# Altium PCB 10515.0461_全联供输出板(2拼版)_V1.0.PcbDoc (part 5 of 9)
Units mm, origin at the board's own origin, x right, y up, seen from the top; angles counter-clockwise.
Board outline 283.88 x 134.8 mm, 2 copper layers (Top Layer, Bottom Layer); 298 components, 0 nets, 1264 pads, 970 vias.
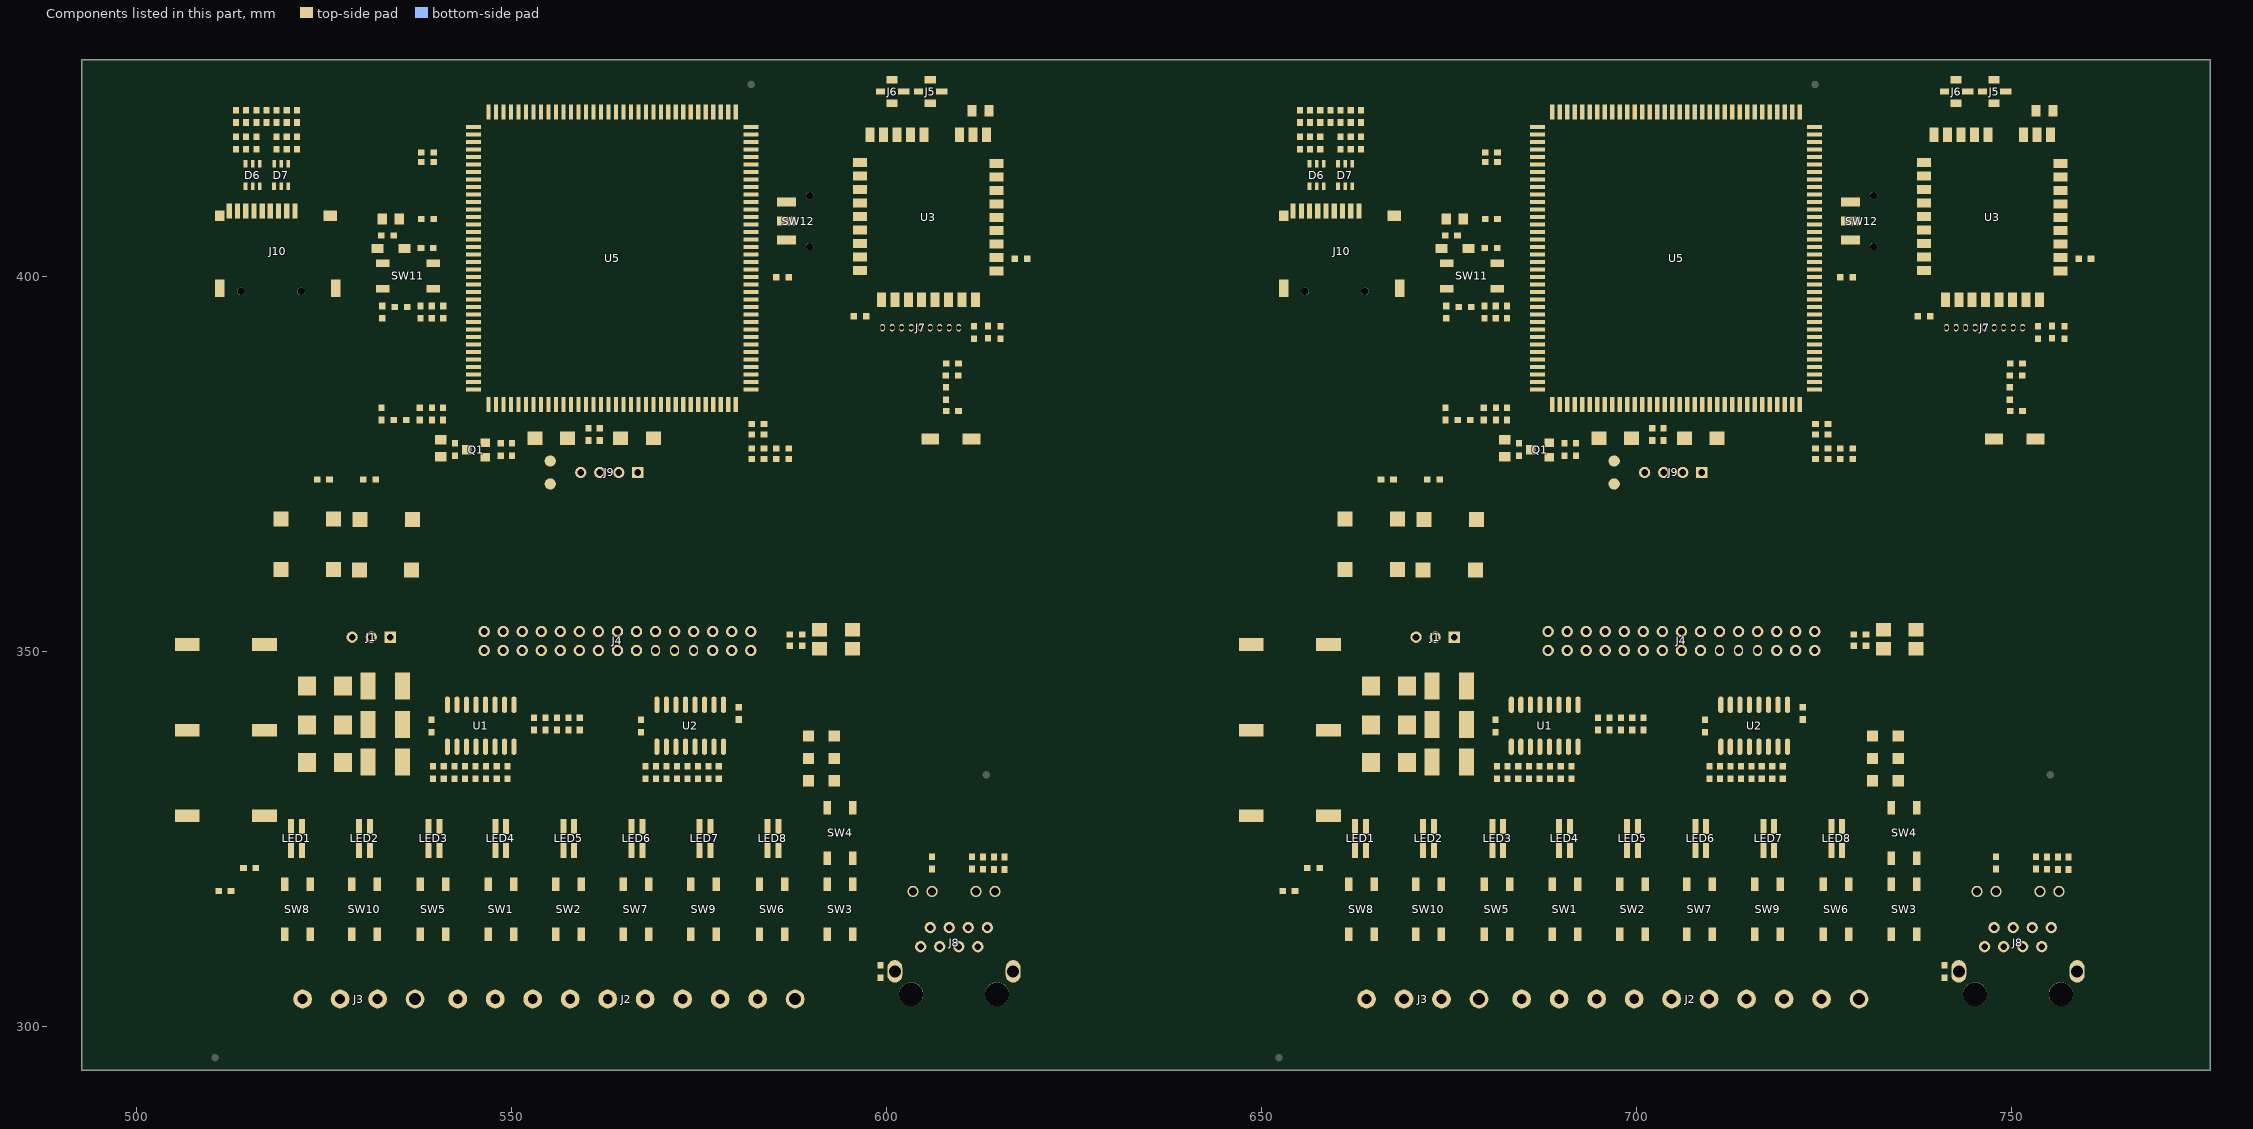
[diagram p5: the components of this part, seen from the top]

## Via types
v1: diameter 0.7, hole 0.4, Top Layer to Bottom Layer, tented both sides, 970 vias

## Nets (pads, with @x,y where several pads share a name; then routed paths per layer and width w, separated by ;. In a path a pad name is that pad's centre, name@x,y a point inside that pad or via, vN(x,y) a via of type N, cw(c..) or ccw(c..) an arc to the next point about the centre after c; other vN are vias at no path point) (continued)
copper on no net: (continued)
  Top Layer w0.65: 536.575,356.309 537.21,356.309 538.46,356.309 538.849,355.92 538.869,355.92 538.944,355.845 539.115,355.674 ; 540.537,375.918 542.277,375.918 542.417,376.058 ; 540.816,380.82 547.865,380.82 ; 540.884,375.699 cw(c541.413,375.169) 541.413,375.918 cw(c541.413,376.666) 540.884,376.137 ; 541.975,375.918 ccw(c541.975,376.461) 542.359,376.077 ; 542.417,377.589 cw(c542.417,375.556) 543.854,376.994 ; 542.417,377.709 543.14,377.709 543.981,376.867 ; 542.441,377.593 cw(c542.762,376.571) 543.52,377.328 ; 543.671,376.867 ccw(c542.923,376.867) 543.452,377.396 ccw(c543.981,377.925) 543.981,377.177 ; 546.671,376.058 548.513,376.058 550.037,376.058 ; 546.719,375.693 cw(c547.6,374.812) 547.6,376.058 ; 547.865,382.91 547.865,381.214 547.865,380.82 ; 548.738,380.82 547.865,380.82 ; v1@585.47,339.443 ccw(c585.47,340.73) 586.38,339.82 ; v1@586.105,339.443 ccw(c586.105,340.73) 587.015,339.82 ; v1@586.13,339.418 cw(c587.723,339.418) 586.597,340.545 ; v1@586.535,342.321 cw(c585.122,340.908) 587.121,340.908 ; v1@586.535,342.357 ccw(c585.122,343.77) 587.121,343.77 ; v1@586.614,339.443 ccw(c586.642,340.659) 587.502,339.799 ; v1@586.638,339.418 cw(c588.231,339.418) 587.105,340.545 ; 587.058,350.755 587.058,352.245 ; v1@587.103,339.436 ccw(c586.141,340.398) 587.502,340.398 ; 587.121,340.561 585.978,339.418 v1(585.47,339.418) ; 587.121,341.069 v1(585.47,339.418) ; 587.121,346.277 cw(c588.712,346.277) 587.587,347.401 cw(c588.549,346.439) 588.549,347.8 ; 587.121,346.904 cw(c587.613,346.904) v1@587.571,347.394 ; 587.195,347.239 cw(c587.569,346.865) v1@587.569,347.394 ; 587.502,343.557 cw(c589.526,343.557) v1@588.095,344.988 ; 587.502,346.455 ccw(c589.526,346.455) v1@588.095,345.024 ; v1@587.594,347.419 cw(c588.123,347.419) 587.749,347.793 ; 588.582,350.721 590.906,350.721 ; 588.625,350.721 cw(c588.625,348.032) 590.526,349.933 ; 589.228,347.8 cw(c589.228,346.135) v1@590.405,347.312 ; 589.845,352.245 ccw(c589.845,353.657) 590.994,352.836 ; v1@590.441,347.312 cw(c591.618,346.135) 591.618,347.8 ; 590.465,353.214 cw(c588.582,354.56) 588.582,352.245 590.652,352.245 ; 590.652,352.499 591.144,352.991 ; 590.906,350.467 591.033,350.34 ; 593.826,348.155 ccw(c591.653,350.328) 594.726,350.338 ; 594.741,348.181 595.401,348.841 595.401,350.34 595.401,352.88 ; 594.868,348.633 cw(c596.242,348.633) 595.579,349.836 ; 594.868,348.689 594.868,352.347 ccw(c596.795,352.347) 595.644,350.801 ; 594.868,349.197 593.471,347.8 593.344,347.8 ; 594.868,350.446 cw(c597.735,350.446) 595.708,352.473 ; 594.868,352.016 cw(c596.165,352.016) 595.248,352.933 ; 594.93,349.259 ccw(c593.855,350.335) 595.376,350.34 ; 594.994,349.933 cw(c594.013,348.952) 595.401,348.952 cw(c596.789,348.952) 595.808,349.933 ; 594.994,350.747 ccw(c594.013,351.728) 595.401,351.728 ccw(c596.789,351.728) 595.808,350.747 ; 594.994,352.473 cw(c594.013,351.492) 595.401,351.492 cw(c596.789,351.492) 595.808,352.473 ; 599.392,419.415 ccw(c598.922,419.885) 599.586,419.885 ccw(c600.25,419.885) 599.78,419.415 ; 599.586,418.871 599.586,421.568 599.16,421.994 599.16,424.635 599.16,425.879 599.466,426.185 600.71,426.185 601.827,426.185 602.26,425.752 602.26,424.635 ; 600.71,423.085 601.386,422.409 601.386,418.871 ; 600.836,422.961 cw(c599.509,421.634) 601.386,421.634 ; 600.911,422.917 cw(c600.729,422.286) 601.386,422.286 ; 601.129,423.038 ccw(c601.626,422.899) 601.261,422.534 ; 601.192,419.415 ccw(c600.722,419.885) 601.386,419.885 ccw(c602.05,419.885) 601.58,419.415 ; 602.992,419.415 ccw(c602.522,419.885) 603.186,419.885 ccw(c603.85,419.885) 603.38,419.415 ; 603.186,418.871 603.186,420.254 602.615,420.825 602.615,424.28 602.26,424.635 ; 604.792,419.415 ccw(c604.322,419.885) 604.986,419.885 ccw(c605.65,419.885) 605.18,419.415 ; 604.986,418.871 604.986,422.281 605.79,423.085 ; 604.986,421.325 cw(c607.3,421.325) 605.664,422.961 ; 604.986,422.109 cw(c605.829,422.109) 605.59,422.917 ; 605.111,422.406 ccw(c604.494,423.024) 605.365,423.075 ; v1(606.298,420.444) v1(607.34,421.486) 607.34,424.635 607.34,425.752 606.907,426.185 605.79,426.185 604.673,426.185 604.24,425.752 604.24,424.635 602.26,424.635 ; 607.904,388.421 ccw(c606.876,389.449) v1@608.33,389.449 ; 607.924,388.669 cw(c609.371,388.669) v1@608.348,389.692 ; 607.924,389.135 cw(c608.497,389.135) v1@608.337,389.686 ; 608.033,312.825 cw(c607.308,312.099) 608.334,312.099 cw(c609.36,312.099) 608.634,312.825 ; 608.334,313.125 608.334,311.855 609.604,310.585 ; 609.179,310.585 ccw(c608.153,310.585) 608.878,311.311 ccw(c609.604,312.036) 609.604,311.01 ; 609.6,388.388 v1(609.6,389.71) 612.902,389.71 613.487,390.295 613.487,391.717 ; 609.6,393.139 609.6,394.282 ; 609.6,394.422 cw(c611.173,394.422) v1@610.061,395.534 ; 609.6,394.925 cw(c610.229,394.925) v1@610.05,395.528 ; 609.849,396.327 cw(c609.379,395.857) 610.043,395.857 cw(c610.707,395.857) 610.238,396.327 ; v1(610.043,395.552) 609.6,395.109 609.6,394.282 ; 610.043,396.871 610.043,394.917 ; v1@610.061,395.57 ccw(c611.637,397.145) 611.637,394.917 ; 610.993,422.247 cw(c611.867,422.247) 611.249,422.865 ; 611.174,421.729 cw(c610.704,421.259) 611.368,421.259 cw(c612.032,421.259) 611.562,421.729 ; 611.174,422.441 ccw(c610.704,422.911) 611.368,422.911 ccw(c612.032,422.911) 611.562,422.441 ; 611.368,418.989 611.368,422.085 611.368,423.609 611.759,424 612.648,424 ; 611.368,420.17 ccw(c612.435,420.17) 611.68,419.415 ; 611.368,422.984 612.384,424 612.648,424 ; 611.643,422.247 cw(c614.086,422.247) 612.359,423.975 ; v1@613.268,420.335 ccw(c612.313,421.29) 613.664,421.29 ; v1@613.275,420.294 cw(c612.99,419.684) 613.664,419.684 ; v1@613.286,420.371 cw(c615.206,420.371) 613.848,421.729 ccw(c614.294,421.283) 613.664,421.283 ; 613.46,421.729 cw(c612.966,421.235) 613.664,421.235 ; 613.48,419.415 cw(c613.95,419.885) 613.286,419.885 cw(c612.622,419.885) 613.092,419.415 ccw(c611.71,420.797) 613.664,420.797 ; 613.62,394.917 614.636,395.933 ; 613.664,422.075 613.664,419.809 613.286,419.431 613.286,418.871 v1(613.286,420.317) 613.286,421.717 613.654,422.085 ; 613.848,421.891 cw(c614.318,421.421) 614.318,422.085 cw(c614.318,422.749) 613.848,422.279 ; 613.848,422.053 cw(c615.484,420.417) 615.484,422.73 ; 613.848,422.117 ccw(c615.129,423.398) 615.129,421.587 ; 614.442,400.477 cw(c613.972,400.007) 614.636,400.007 cw(c615.3,400.007) 614.83,400.477 ; 614.636,402.471 614.774,402.333 617.043,402.333 617.068,402.333 ; 614.636,409.671 616.563,409.671 ; 614.68,404.315 v1(616.563,404.315) 616.563,409.671 ; 615.18,400.477 cw(c615.65,400.007) 615.65,400.671 cw(c615.65,401.335) 615.18,400.865 ; 615.18,402.665 ccw(c615.983,403.468) 615.983,402.333 ; 615.18,404.077 cw(c615.756,403.501) 615.756,404.315 ; 615.18,409.477 cw(c615.65,409.007) 615.65,409.671 cw(c615.65,410.335) 615.18,409.865 ; 615.679,404.315 ccw(c615.679,406.11) 616.948,404.841 ccw(c616.599,405.19) 617.093,405.19 ; v1(616.116,400.671) 614.636,400.671 614.636,395.933 ; v1@616.563,404.175 cw(c617.243,404.175) v1@616.976,404.8 ; v1@616.563,404.293 617.093,404.823 617.093,420.803 616.563,421.333 ; 616.563,405.856 ccw(c617.999,405.856) v1@616.984,404.841 ; 616.563,420.698 615.674,421.587 614.152,421.587 613.654,422.085 ; 616.712,422.73 616.204,422.73 ; 617.033,421.46 616.204,422.289 616.204,422.73 ; v1(618.744,395.044) 618.744,423.238 617.982,424 617.347,424 ; 618.744,402.918 618.363,403.299 618.363,423.111 617.474,424 617.347,424 ; 678.475,356.309 679.11,356.309 680.36,356.309 680.749,355.92 680.768,355.92 680.843,355.845 681.015,355.674 ; 682.437,375.918 684.177,375.918 684.317,376.058 ; 682.716,380.82 689.765,380.82 ; 682.784,375.699 cw(c683.313,375.169) 683.313,375.918 cw(c683.313,376.666) 682.784,376.137 ; 683.875,375.918 ccw(c683.875,376.461) 684.259,376.077 ; 684.317,377.589 cw(c684.317,375.556) 685.754,376.994 ; 684.317,377.709 685.04,377.709 685.881,376.867 ; 684.341,377.593 cw(c684.662,376.571) 685.42,377.328 ; 685.571,376.867 ccw(c684.823,376.867) 685.352,377.396 ccw(c685.881,377.925) 685.881,377.177 ; 688.571,376.058 690.413,376.058 691.937,376.058 ; 688.619,375.693 cw(c689.5,374.812) 689.5,376.058 ; 689.765,382.91 689.765,381.214 689.765,380.82 ; 690.638,380.82 689.765,380.82 ; v1@727.37,339.443 ccw(c727.37,340.73) 728.28,339.82 ; v1@728.005,339.443 ccw(c728.005,340.73) 728.915,339.82 ; v1@728.03,339.418 cw(c729.623,339.418) 728.497,340.545 ; v1@728.435,342.321 cw(c727.022,340.908) 729.021,340.908 ; v1@728.435,342.357 ccw(c727.022,343.77) 729.021,343.77 ; v1@728.514,339.443 ccw(c728.542,340.659) 729.402,339.799 ; v1@728.538,339.418 cw(c730.131,339.418) 729.005,340.545 ; 728.957,350.755 728.957,352.245 ; v1@729.003,339.436 ccw(c728.041,340.398) 729.402,340.398 ; 729.021,340.561 727.878,339.418 v1(727.37,339.418) ; 729.021,341.069 v1(727.37,339.418) ; 729.021,346.277 cw(c730.612,346.277) 729.487,347.401 cw(c730.449,346.439) 730.449,347.8 ; 729.021,346.904 cw(c729.513,346.904) v1@729.471,347.394 ; 729.095,347.239 cw(c729.469,346.865) v1@729.469,347.394 ; 729.402,343.557 cw(c731.426,343.557) v1@729.995,344.988 ; 729.402,346.455 ccw(c731.426,346.455) v1@729.995,345.024 ; v1@729.494,347.419 cw(c730.023,347.419) 729.649,347.793 ; 730.481,350.721 732.806,350.721 ; 730.525,350.721 cw(c730.525,348.032) 732.426,349.933 ; 731.128,347.8 cw(c731.128,346.135) v1@732.305,347.312 ; 731.745,352.245 ccw(c731.745,353.657) 732.894,352.836 ; v1@732.341,347.312 cw(c733.518,346.135) 733.518,347.8 ; 732.365,353.214 cw(c730.482,354.56) 730.482,352.245 732.552,352.245 ; 732.552,352.499 733.044,352.991 ; 732.806,350.467 732.933,350.34 ; 735.726,348.155 ccw(c733.553,350.328) 736.626,350.338 ; 736.641,348.181 737.301,348.841 737.301,350.34 737.301,352.88 ; 736.768,348.633 cw(c738.142,348.633) 737.479,349.836 ; 736.768,348.689 736.768,352.347 ccw(c738.695,352.347) 737.544,350.801 ; 736.768,349.197 735.371,347.8 735.244,347.8 ; 736.768,350.446 cw(c739.635,350.446) 737.608,352.473 ; 736.768,352.016 cw(c738.065,352.016) 737.148,352.933 ; 736.83,349.259 ccw(c735.755,350.335) 737.276,350.34 ; 736.894,349.933 cw(c735.913,348.952) 737.301,348.952 cw(c738.689,348.952) 737.708,349.933 ; 736.894,350.747 ccw(c735.913,351.728) 737.301,351.728 ccw(c738.689,351.728) 737.708,350.747 ; 736.894,352.473 cw(c735.913,351.492) 737.301,351.492 cw(c738.689,351.492) 737.708,352.473 ; 741.292,419.415 ccw(c740.822,419.885) 741.486,419.885 ccw(c742.15,419.885) 741.68,419.415 ; 741.486,418.871 741.486,421.568 741.06,421.994 741.06,424.635 741.06,425.879 741.366,426.185 742.61,426.185 743.727,426.185 744.16,425.752 744.16,424.635 ; 742.61,423.085 743.286,422.409 743.286,418.871 ; 742.736,422.961 cw(c741.409,421.634) 743.286,421.634 ; 742.811,422.917 cw(c742.629,422.286) 743.286,422.286 ; 743.029,423.038 ccw(c743.526,422.899) 743.161,422.534 ; 743.092,419.415 ccw(c742.622,419.885) 743.286,419.885 ccw(c743.95,419.885) 743.48,419.415 ; 744.892,419.415 ccw(c744.422,419.885) 745.086,419.885 ccw(c745.75,419.885) 745.28,419.415 ; 745.086,418.871 745.086,420.254 744.515,420.825 744.515,424.28 744.16,424.635 ; 746.692,419.415 ccw(c746.222,419.885) 746.886,419.885 ccw(c747.55,419.885) 747.08,419.415 ; 746.886,418.871 746.886,422.281 747.69,423.085 ; 746.886,421.325 cw(c749.2,421.325) 747.564,422.961 ; 746.886,422.109 cw(c747.729,422.109) 747.49,422.917 ; 747.011,422.406 ccw(c746.394,423.024) 747.265,423.075 ; v1(748.198,420.444) v1(749.24,421.486) 749.24,424.635 749.24,425.752 748.807,426.185 747.69,426.185 746.573,426.185 746.14,425.752 746.14,424.635 744.16,424.635 ; 749.804,388.421 ccw(c748.776,389.449) v1@750.23,389.449 ; 749.824,388.669 cw(c751.271,388.669) v1@750.248,389.692 ; 749.824,389.135 cw(c750.397,389.135) v1@750.237,389.686 ; 749.933,312.825 cw(c749.208,312.099) 750.234,312.099 cw(c751.26,312.099) 750.534,312.825 ; 750.234,313.125 750.234,311.855 751.504,310.585 ; 751.079,310.585 ccw(c750.053,310.585) 750.778,311.311 ccw(c751.504,312.036) 751.504,311.01 ; 751.5,388.388 v1(751.5,389.71) 754.802,389.71 755.387,390.295 755.387,391.717 ; 751.5,393.139 751.5,394.282 ; 751.5,394.422 cw(c753.073,394.422) v1@751.961,395.534 ; 751.5,394.925 cw(c752.129,394.925) v1@751.95,395.528 ; 751.749,396.327 cw(c751.279,395.857) 751.943,395.857 cw(c752.607,395.857) 752.138,396.327 ; v1(751.943,395.552) 751.5,395.109 751.5,394.282 ; 751.943,396.871 751.943,394.917 ; v1@751.961,395.57 ccw(c753.537,397.145) 753.537,394.917 ; 752.893,422.247 cw(c753.767,422.247) 753.149,422.865 ; 753.074,421.729 cw(c752.604,421.259) 753.268,421.259 cw(c753.932,421.259) 753.462,421.729 ; 753.074,422.441 ccw(c752.604,422.911) 753.268,422.911 ccw(c753.932,422.911) 753.462,422.441 ; 753.268,418.989 753.268,422.085 753.268,423.609 753.659,424 754.548,424 ; 753.268,420.17 ccw(c754.335,420.17) 753.58,419.415 ; 753.268,422.984 754.284,424 754.548,424 ; 753.543,422.247 cw(c755.986,422.247) 754.259,423.975 ; v1@755.168,420.335 ccw(c754.213,421.29) 755.564,421.29 ; v1@755.175,420.294 cw(c754.89,419.684) 755.564,419.684 ; v1@755.186,420.371 cw(c757.106,420.371) 755.748,421.729 ccw(c756.194,421.283) 755.564,421.283 ; 755.36,421.729 cw(c754.866,421.235) 755.564,421.235 ; 755.38,419.415 cw(c755.85,419.885) 755.186,419.885 cw(c754.522,419.885) 754.992,419.415 ccw(c753.61,420.797) 755.564,420.797 ; 755.52,394.917 756.536,395.933 ; 755.564,422.075 755.564,419.809 755.186,419.431 755.186,418.871 v1(755.186,420.317) 755.186,421.717 755.554,422.085 ; 755.748,421.891 cw(c756.218,421.421) 756.218,422.085 cw(c756.218,422.749) 755.748,422.279 ; 755.748,422.053 cw(c757.384,420.417) 757.384,422.73 ; 755.748,422.117 ccw(c757.029,423.398) 757.029,421.587 ; 756.342,400.477 cw(c755.872,400.007) 756.536,400.007 cw(c757.2,400.007) 756.73,400.477 ; 756.536,402.471 756.674,402.333 758.943,402.333 758.968,402.333 ; 756.536,409.671 758.463,409.671 ; 756.58,404.315 v1(758.463,404.315) 758.463,409.671 ; 757.08,400.477 cw(c757.55,400.007) 757.55,400.671 cw(c757.55,401.335) 757.08,400.865 ; 757.08,402.665 ccw(c757.883,403.468) 757.883,402.333 ; 757.08,404.077 cw(c757.656,403.501) 757.656,404.315 ; 757.08,409.477 cw(c757.55,409.007) 757.55,409.671 cw(c757.55,410.335) 757.08,409.865 ; 757.579,404.315 ccw(c757.579,406.11) 758.848,404.841 ccw(c758.499,405.19) 758.993,405.19 ; v1(758.016,400.671) 756.536,400.671 756.536,395.933 ; v1@758.463,404.175 cw(c759.143,404.175) v1@758.876,404.8 ; v1@758.463,404.293 758.993,404.823 758.993,420.803 758.463,421.333 ; 758.463,405.856 ccw(c759.899,405.856) v1@758.884,404.841 ; 758.463,420.698 757.574,421.587 756.052,421.587 755.554,422.085 ; 758.612,422.73 758.104,422.73 ; 758.933,421.46 758.104,422.289 758.104,422.73 ; v1(760.644,395.044) 760.644,423.238 759.882,424 759.247,424 ; 760.644,402.918 760.263,403.299 760.263,423.111 759.374,424 759.247,424 ; v1(585.47,339.418) v1(586.613,339.418) ; v1(586.613,339.418) 587.121,339.926 587.121,347.165 587.756,347.8 593.344,347.8 ; v1(586.613,339.418) v1(587.121,339.418) 587.502,339.799 ; 587.502,339.799 587.502,346.657 588.137,347.292 593.852,347.292 594.893,348.333 594.36,347.8 593.344,347.8 ; 609.6,394.282 610.043,394.725 610.043,394.917 ; 610.043,394.917 614.172,394.917 614.636,395.381 614.636,395.933 ; 612.648,424 617.347,424 ; 613.654,422.085 615.811,422.085 616.563,421.333 ; 613.654,422.085 613.654,422.339 614.045,422.73 616.204,422.73 ; 616.563,409.671 616.563,421.333 ; v1(727.37,339.418) v1(728.513,339.418) ; v1(728.513,339.418) 729.021,339.926 729.021,347.165 729.656,347.8 735.244,347.8 ; v1(728.513,339.418) v1(729.021,339.418) 729.402,339.799 ; 729.402,339.799 729.402,346.657 730.037,347.292 735.752,347.292 736.793,348.333 736.26,347.8 735.244,347.8 ; 751.5,394.282 751.943,394.725 751.943,394.917 ; 751.943,394.917 756.072,394.917 756.536,395.381 756.536,395.933 ; 754.548,424 759.247,424 ; 755.554,422.085 757.711,422.085 758.463,421.333 ; 755.554,422.085 755.554,422.339 755.945,422.73 758.104,422.73 ; 758.463,409.671 758.463,421.333 ; v1@587.587,347.437 ccw(c587.936,347.786) 587.936,347.292 cw(c587.936,347.786) v1@587.587,347.437 ; 607.924,388.363 608.33,388.769 v1(608.33,389.71) 607.924,389.304 607.924,388.363 ; v1@729.487,347.437 ccw(c729.836,347.786) 729.836,347.292 cw(c729.836,347.786) v1@729.487,347.437 ; 749.824,388.363 750.23,388.769 v1(750.23,389.71) 749.824,389.304 749.824,388.363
